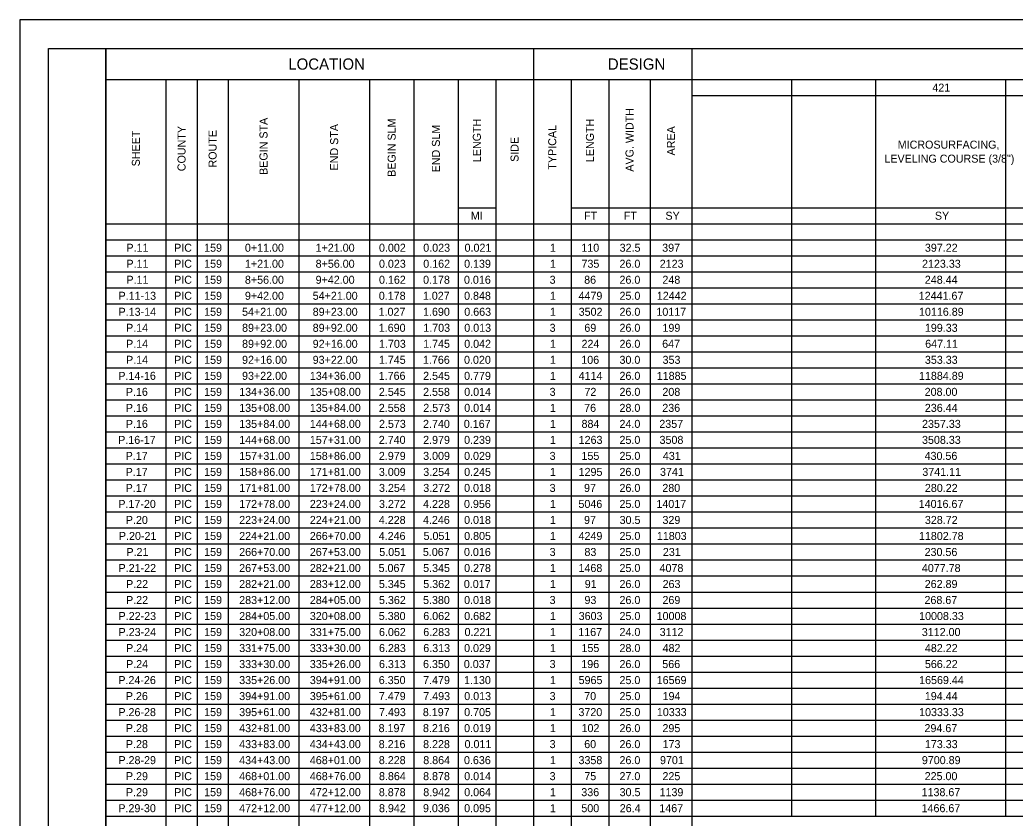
# Model space of a CAD drawing. Extents: x 0 to 34, y 0 to 22.
# Drawn here: x 0 to 17.4, y 8.04 to 22 of the extents above; entities that cross this region are included whole.
import ezdxf

# ---------------------------------------------------------------- set-up
doc = ezdxf.new("R2010")
doc.units = 0
for name, color, linetype in [('SH_Border', 7, 'Continuous'), ('SH_Cut_Line', 7, 'Continuous'), ('SH_Text', 7, 'Continuous')]:
    doc.layers.add(name, color=color, linetype=linetype)

msp = doc.modelspace()

# ---------------------------------------------------------------- linework, layer by layer
at = {"layer": 'SH_Border'}
for points in [[(0.5, 21.5), (1.5, 21.5), (1.5, 0.5), (0.5, 0.5)], [(1.5, 21.5), (33.5, 21.5), (33.5, 0.5), (1.5, 0.5)]]:
    msp.add_lwpolyline(points, close=True, dxfattribs=at)
at = {"layer": 'SH_Cut_Line'}
msp.add_lwpolyline([(0, 0), (34, 0), (34, 22), (0, 22)], close=True, dxfattribs=at)
at = {"layer": 'SH_Text'}
for p, q in [((1.5, 21.5), (32.004, 21.5)), ((1.5, 21.5), (1.5, 3.876)), ((8.978, 21.5), (8.978, 0.796)), ((11.745, 21.5), (11.745, 0.516)), ((1.5, 20.956), (32.004, 20.956)), ((2.554, 20.956), (2.554, 0.796)), ((3.098, 20.956), (3.098, 0.796)), ((3.641, 20.956), (3.641, 0.796)), ((4.876, 20.956), (4.876, 0.796)), ((6.112, 20.956), (6.112, 0.796)), ((6.886, 20.956), (6.886, 0.796)), ((7.66, 20.956), (7.66, 0.796)), ((8.319, 20.956), (8.319, 0.796)), ((9.636, 20.956), (9.636, 3.316)), ((10.295, 20.956), (10.295, 3.316)), ((11.02, 20.956), (11.02, 0.796)), ((13.491, 20.956), (13.491, 8.076)), ((14.956, 20.956), (14.956, 8.076)), ((17.229, 20.956), (17.229, 8.076)), ((11.745, 20.676), (27.474, 20.676)), ((7.66, 18.716), (8.319, 18.716)), ((9.636, 18.716), (27.474, 18.716)), ((1.5, 18.436), (32.004, 18.436)), ((1.5, 18.156), (32.004, 18.156)), ((1.5, 17.876), (32.004, 17.876)), ((1.5, 17.596), (32.004, 17.596)), ((1.5, 17.316), (32.004, 17.316)), ((1.5, 17.036), (32.004, 17.036)), ((1.5, 16.756), (32.004, 16.756)), ((1.5, 16.476), (32.004, 16.476)), ((1.5, 16.196), (32.004, 16.196)), ((1.5, 15.916), (32.004, 15.916)), ((1.5, 15.636), (32.004, 15.636)), ((1.5, 15.356), (32.004, 15.356)), ((1.5, 15.076), (32.004, 15.076)), ((1.5, 14.796), (32.004, 14.796)), ((1.5, 14.516), (32.004, 14.516)), ((1.5, 14.236), (32.004, 14.236)), ((1.5, 13.956), (32.004, 13.956)), ((1.5, 13.676), (32.004, 13.676)), ((1.5, 13.396), (32.004, 13.396)), ((1.5, 13.116), (32.004, 13.116)), ((1.5, 12.836), (32.004, 12.836)), ((1.5, 12.556), (32.004, 12.556)), ((1.5, 12.276), (32.004, 12.276)), ((1.5, 11.996), (32.004, 11.996)), ((1.5, 11.716), (32.004, 11.716)), ((1.5, 11.436), (32.004, 11.436)), ((1.5, 11.156), (32.004, 11.156)), ((1.5, 10.876), (32.004, 10.876)), ((1.5, 10.596), (32.004, 10.596)), ((1.5, 10.316), (32.004, 10.316)), ((1.5, 10.036), (32.004, 10.036)), ((1.5, 9.756), (32.004, 9.756)), ((1.5, 9.476), (32.004, 9.476)), ((1.5, 9.196), (32.004, 9.196)), ((1.5, 8.916), (32.004, 8.916)), ((1.5, 8.636), (32.004, 8.636)), ((1.5, 8.356), (32.004, 8.356)), ((1.5, 8.076), (32.004, 8.076))]:
    msp.add_line(p, q, dxfattribs=at)

# ---------------------------------------------------------------- texts
for s, height, p in [('LOCATION', 0.196, (4.692, 21.13)), ('DESIGN', 0.196, (10.279, 21.13)), ('421', 0.14, (15.952, 20.746)), ('MICROSURFACING, ', 0.14, (15.347, 19.749)), ('LEVELING COURSE (3/8")', 0.14, (15.114, 19.504)), ('MI', 0.14, (7.883, 18.506)), ('FT', 0.14, (9.865, 18.506)), ('FT', 0.14, (10.557, 18.506)), ('SY', 0.14, (11.286, 18.506)), ('SY', 0.14, (15.997, 18.506)), ('P.11', 0.14, (1.862, 17.946)), ('PIC', 0.14, (2.696, 17.946)), ('159', 0.14, (3.221, 17.946)), ('0+11.00', 0.14, (3.934, 17.946)), ('1+21.00', 0.14, (5.17, 17.946)), ('0.002', 0.14, (6.278, 17.946)), ('0.023', 0.14, (7.052, 17.946)), ('0.021', 0.14, (7.774, 17.946)), ('1', 0.14, (9.267, 17.946)), ('110', 0.14, (9.816, 17.946)), ('32.5', 0.14, (10.485, 17.946)), ('397', 0.14, (11.229, 17.946)), ('397.22', 0.14, (15.822, 17.946)), ('P.11', 0.14, (1.862, 17.666)), ('PIC', 0.14, (2.696, 17.666)), ('159', 0.14, (3.221, 17.666)), ('1+21.00', 0.14, (3.934, 17.666)), ('8+56.00', 0.14, (5.17, 17.666)), ('0.023', 0.14, (6.278, 17.666)), ('0.162', 0.14, (7.052, 17.666)), ('0.139', 0.14, (7.766, 17.666)), ('1', 0.14, (9.267, 17.666)), ('735', 0.14, (9.818, 17.666)), ('26.0', 0.14, (10.483, 17.666)), ('2123', 0.14, (11.186, 17.666)), ('2123.33', 0.14, (15.772, 17.666)), ('P.11', 0.14, (1.862, 17.386)), ('PIC', 0.14, (2.696, 17.386)), ('159', 0.14, (3.221, 17.386)), ('8+56.00', 0.14, (3.934, 17.386)), ('9+42.00', 0.14, (5.17, 17.386)), ('0.162', 0.14, (6.278, 17.386)), ('0.178', 0.14, (7.049, 17.386)), ('0.016', 0.14, (7.764, 17.386)), ('3', 0.14, (9.261, 17.386)), ('86', 0.14, (9.865, 17.386)), ('26.0', 0.14, (10.483, 17.386)), ('248', 0.14, (11.233, 17.386)), ('248.44', 0.14, (15.821, 17.386)), ('P.11-13', 0.14, (1.725, 17.106)), ('PIC', 0.14, (2.696, 17.106)), ('159', 0.14, (3.221, 17.106)), ('9+42.00', 0.14, (3.934, 17.106)), ('54+21.00', 0.14, (5.119, 17.106)), ('0.178', 0.14, (6.275, 17.106)), ('1.027', 0.14, (7.045, 17.106)), ('0.848', 0.14, (7.766, 17.106)), ('1', 0.14, (9.267, 17.106)), ('4479', 0.14, (9.767, 17.106)), ('25.0', 0.14, (10.483, 17.106)), ('12442', 0.14, (11.135, 17.106)), ('12441.67', 0.14, (15.714, 17.106)), ('P.13-14', 0.14, (1.725, 16.826)), ('PIC', 0.14, (2.696, 16.826)), ('159', 0.14, (3.221, 16.826)), ('54+21.00', 0.14, (3.884, 16.826)), ('89+23.00', 0.14, (5.119, 16.826)), ('1.027', 0.14, (6.271, 16.826)), ('1.690', 0.14, (7.048, 16.826)), ('0.663', 0.14, (7.769, 16.826)), ('1', 0.14, (9.267, 16.826)), ('3502', 0.14, (9.769, 16.826)), ('26.0', 0.14, (10.483, 16.826)), ('10117', 0.14, (11.128, 16.826)), ('10116.89', 0.14, (15.719, 16.826)), ('P.14', 0.14, (1.856, 16.546)), ('PIC', 0.14, (2.696, 16.546)), ('159', 0.14, (3.221, 16.546)), ('89+23.00', 0.14, (3.884, 16.546)), ('89+92.00', 0.14, (5.119, 16.546)), ('1.690', 0.14, (6.274, 16.546)), ('1.703', 0.14, (7.052, 16.546)), ('0.013', 0.14, (7.769, 16.546)), ('3', 0.14, (9.261, 16.546)), ('69', 0.14, (9.868, 16.546)), ('26.0', 0.14, (10.483, 16.546)), ('199', 0.14, (11.234, 16.546)), ('199.33', 0.14, (15.822, 16.546)), ('P.14', 0.14, (1.856, 16.266)), ('PIC', 0.14, (2.696, 16.266)), ('159', 0.14, (3.221, 16.266)), ('89+92.00', 0.14, (3.884, 16.266)), ('92+16.00', 0.14, (5.119, 16.266)), ('1.703', 0.14, (6.278, 16.266)), ('1.745', 0.14, (7.05, 16.266)), ('0.042', 0.14, (7.768, 16.266)), ('1', 0.14, (9.267, 16.266)), ('224', 0.14, (9.819, 16.266)), ('26.0', 0.14, (10.483, 16.266)), ('647', 0.14, (11.229, 16.266)), ('647.11', 0.14, (15.827, 16.266)), ('P.14', 0.14, (1.856, 15.986)), ('PIC', 0.14, (2.696, 15.986)), ('159', 0.14, (3.221, 15.986)), ('92+16.00', 0.14, (3.884, 15.986)), ('93+22.00', 0.14, (5.119, 15.986)), ('1.745', 0.14, (6.276, 15.986)), ('1.766', 0.14, (7.047, 15.986)), ('0.020', 0.14, (7.765, 15.986)), ('1', 0.14, (9.267, 15.986)), ('106', 0.14, (9.815, 15.986)), ('30.0', 0.14, (10.483, 15.986)), ('353', 0.14, (11.236, 15.986)), ('353.33', 0.14, (15.822, 15.986)), ('P.14-16', 0.14, (1.721, 15.706)), ('PIC', 0.14, (2.696, 15.706)), ('159', 0.14, (3.221, 15.706)), ('93+22.00', 0.14, (3.884, 15.706)), ('134+36.00', 0.14, (5.069, 15.706)), ('1.766', 0.14, (6.273, 15.706)), ('2.545', 0.14, (7.05, 15.706)), ('0.779', 0.14, (7.766, 15.706)), ('1', 0.14, (9.267, 15.706)), ('4114', 0.14, (9.769, 15.706)), ('26.0', 0.14, (10.483, 15.706)), ('11885', 0.14, (11.134, 15.706)), ('11884.89', 0.14, (15.719, 15.706)), ('P.16', 0.14, (1.852, 15.426)), ('PIC', 0.14, (2.696, 15.426)), ('159', 0.14, (3.221, 15.426)), ('134+36.00', 0.14, (3.834, 15.426)), ('135+08.00', 0.14, (5.069, 15.426)), ('2.545', 0.14, (6.276, 15.426)), ('2.558', 0.14, (7.049, 15.426)), ('0.014', 0.14, (7.768, 15.426)), ('3', 0.14, (9.261, 15.426)), ('72', 0.14, (9.87, 15.426)), ('26.0', 0.14, (10.483, 15.426)), ('208', 0.14, (11.233, 15.426)), ('208.00', 0.14, (15.818, 15.426)), ('P.16', 0.14, (1.852, 15.146)), ('PIC', 0.14, (2.696, 15.146)), ('159', 0.14, (3.221, 15.146)), ('135+08.00', 0.14, (3.834, 15.146)), ('135+84.00', 0.14, (5.069, 15.146)), ('2.558', 0.14, (6.275, 15.146)), ('2.573', 0.14, (7.052, 15.146)), ('0.014', 0.14, (7.768, 15.146)), ('1', 0.14, (9.267, 15.146)), ('76', 0.14, (9.865, 15.146)), ('28.0', 0.14, (10.483, 15.146)), ('236', 0.14, (11.231, 15.146)), ('236.44', 0.14, (15.821, 15.146)), ('P.16', 0.14, (1.852, 14.866)), ('PIC', 0.14, (2.696, 14.866)), ('159', 0.14, (3.221, 14.866)), ('135+84.00', 0.14, (3.834, 14.866)), ('144+68.00', 0.14, (5.069, 14.866)), ('2.573', 0.14, (6.278, 14.866)), ('2.740', 0.14, (7.048, 14.866)), ('0.167', 0.14, (7.761, 14.866)), ('1', 0.14, (9.267, 14.866)), ('884', 0.14, (9.819, 14.866)), ('24.0', 0.14, (10.483, 14.866)), ('2357', 0.14, (11.179, 14.866)), ('2357.33', 0.14, (15.772, 14.866)), ('P.16-17', 0.14, (1.718, 14.586)), ('PIC', 0.14, (2.696, 14.586)), ('159', 0.14, (3.221, 14.586)), ('144+68.00', 0.14, (3.834, 14.586)), ('157+31.00', 0.14, (5.069, 14.586)), ('2.740', 0.14, (6.274, 14.586)), ('2.979', 0.14, (7.05, 14.586)), ('0.239', 0.14, (7.766, 14.586)), ('1', 0.14, (9.267, 14.586)), ('1263', 0.14, (9.769, 14.586)), ('25.0', 0.14, (10.483, 14.586)), ('3508', 0.14, (11.183, 14.586)), ('3508.33', 0.14, (15.772, 14.586)), ('P.17', 0.14, (1.849, 14.306)), ('PIC', 0.14, (2.696, 14.306)), ('159', 0.14, (3.221, 14.306)), ('157+31.00', 0.14, (3.834, 14.306)), ('158+86.00', 0.14, (5.069, 14.306)), ('2.979', 0.14, (6.276, 14.306)), ('3.009', 0.14, (7.05, 14.306)), ('0.029', 0.14, (7.766, 14.306)), ('3', 0.14, (9.261, 14.306)), ('155', 0.14, (9.818, 14.306)), ('25.0', 0.14, (10.483, 14.306)), ('431', 0.14, (11.241, 14.306)), ('430.56', 0.14, (15.817, 14.306)), ('P.17', 0.14, (1.849, 14.026)), ('PIC', 0.14, (2.696, 14.026)), ('159', 0.14, (3.221, 14.026)), ('158+86.00', 0.14, (3.834, 14.026)), ('171+81.00', 0.14, (5.069, 14.026)), ('3.009', 0.14, (6.276, 14.026)), ('3.254', 0.14, (7.052, 14.026)), ('0.245', 0.14, (7.767, 14.026)), ('1', 0.14, (9.267, 14.026)), ('1295', 0.14, (9.768, 14.026)), ('26.0', 0.14, (10.483, 14.026)), ('3741', 0.14, (11.191, 14.026)), ('3741.11', 0.14, (15.777, 14.026)), ('P.17', 0.14, (1.849, 13.746)), ('PIC', 0.14, (2.696, 13.746)), ('159', 0.14, (3.221, 13.746)), ('171+81.00', 0.14, (3.834, 13.746)), ('172+78.00', 0.14, (5.069, 13.746)), ('3.254', 0.14, (6.278, 13.746)), ('3.272', 0.14, (7.052, 13.746)), ('0.018', 0.14, (7.766, 13.746)), ('3', 0.14, (9.261, 13.746)), ('97', 0.14, (9.863, 13.746)), ('26.0', 0.14, (10.483, 13.746)), ('280', 0.14, (11.232, 13.746)), ('280.22', 0.14, (15.822, 13.746)), ('P.17-20', 0.14, (1.721, 13.466)), ('PIC', 0.14, (2.696, 13.466)), ('159', 0.14, (3.221, 13.466)), ('172+78.00', 0.14, (3.834, 13.466)), ('223+24.00', 0.14, (5.069, 13.466)), ('3.272', 0.14, (6.278, 13.466)), ('4.228', 0.14, (7.049, 13.466)), ('0.956', 0.14, (7.764, 13.466)), ('1', 0.14, (9.267, 13.466)), ('5046', 0.14, (9.765, 13.466)), ('25.0', 0.14, (10.483, 13.466)), ('14017', 0.14, (11.128, 13.466)), ('14016.67', 0.14, (15.714, 13.466)), ('P.20', 0.14, (1.852, 13.186)), ('PIC', 0.14, (2.696, 13.186)), ('159', 0.14, (3.221, 13.186)), ('223+24.00', 0.14, (3.834, 13.186)), ('224+21.00', 0.14, (5.069, 13.186)), ('4.228', 0.14, (6.275, 13.186)), ('4.246', 0.14, (7.047, 13.186)), ('0.018', 0.14, (7.766, 13.186)), ('1', 0.14, (9.267, 13.186)), ('97', 0.14, (9.863, 13.186)), ('30.5', 0.14, (10.485, 13.186)), ('329', 0.14, (11.234, 13.186)), ('328.72', 0.14, (15.822, 13.186)), ('P.20-21', 0.14, (1.731, 12.906)), ('PIC', 0.14, (2.696, 12.906)), ('159', 0.14, (3.221, 12.906)), ('224+21.00', 0.14, (3.834, 12.906)), ('266+70.00', 0.14, (5.069, 12.906)), ('4.246', 0.14, (6.273, 12.906)), ('5.051', 0.14, (7.057, 12.906)), ('0.805', 0.14, (7.767, 12.906)), ('1', 0.14, (9.267, 12.906)), ('4249', 0.14, (9.767, 12.906)), ('25.0', 0.14, (10.483, 12.906)), ('11803', 0.14, (11.136, 12.906)), ('11802.78', 0.14, (15.718, 12.906)), ('P.21', 0.14, (1.862, 12.626)), ('PIC', 0.14, (2.696, 12.626)), ('159', 0.14, (3.221, 12.626)), ('266+70.00', 0.14, (3.834, 12.626)), ('267+53.00', 0.14, (5.069, 12.626)), ('5.051', 0.14, (6.283, 12.626)), ('5.067', 0.14, (7.045, 12.626)), ('0.016', 0.14, (7.764, 12.626)), ('3', 0.14, (9.261, 12.626)), ('83', 0.14, (9.87, 12.626)), ('25.0', 0.14, (10.483, 12.626)), ('231', 0.14, (11.241, 12.626)), ('230.56', 0.14, (15.817, 12.626)), ('P.21-22', 0.14, (1.725, 12.346)), ('PIC', 0.14, (2.696, 12.346)), ('159', 0.14, (3.221, 12.346)), ('267+53.00', 0.14, (3.834, 12.346)), ('282+21.00', 0.14, (5.069, 12.346)), ('5.067', 0.14, (6.271, 12.346)), ('5.345', 0.14, (7.05, 12.346)), ('0.278', 0.14, (7.766, 12.346)), ('1', 0.14, (9.267, 12.346)), ('1468', 0.14, (9.766, 12.346)), ('25.0', 0.14, (10.483, 12.346)), ('4078', 0.14, (11.183, 12.346)), ('4077.78', 0.14, (15.769, 12.346)), ('P.22', 0.14, (1.856, 12.066)), ('PIC', 0.14, (2.696, 12.066)), ('159', 0.14, (3.221, 12.066)), ('282+21.00', 0.14, (3.834, 12.066)), ('283+12.00', 0.14, (5.069, 12.066)), ('5.345', 0.14, (6.276, 12.066)), ('5.362', 0.14, (7.052, 12.066)), ('0.017', 0.14, (7.761, 12.066)), ('1', 0.14, (9.267, 12.066)), ('91', 0.14, (9.875, 12.066)), ('26.0', 0.14, (10.483, 12.066)), ('263', 0.14, (11.236, 12.066)), ('262.89', 0.14, (15.819, 12.066)), ('P.22', 0.14, (1.856, 11.786)), ('PIC', 0.14, (2.696, 11.786)), ('159', 0.14, (3.221, 11.786)), ('283+12.00', 0.14, (3.834, 11.786)), ('284+05.00', 0.14, (5.069, 11.786)), ('5.362', 0.14, (6.278, 11.786)), ('5.380', 0.14, (7.048, 11.786)), ('0.018', 0.14, (7.766, 11.786)), ('3', 0.14, (9.261, 11.786)), ('93', 0.14, (9.87, 11.786)), ('26.0', 0.14, (10.483, 11.786)), ('269', 0.14, (11.234, 11.786)), ('268.67', 0.14, (15.815, 11.786)), ('P.22-23', 0.14, (1.725, 11.506)), ('PIC', 0.14, (2.696, 11.506)), ('159', 0.14, (3.221, 11.506)), ('284+05.00', 0.14, (3.834, 11.506)), ('320+08.00', 0.14, (5.069, 11.506)), ('5.380', 0.14, (6.274, 11.506)), ('6.062', 0.14, (7.052, 11.506)), ('0.682', 0.14, (7.768, 11.506)), ('1', 0.14, (9.267, 11.506)), ('3603', 0.14, (9.769, 11.506)), ('25.0', 0.14, (10.483, 11.506)), ('10008', 0.14, (11.132, 11.506)), ('10008.33', 0.14, (15.721, 11.506)), ('P.23-24', 0.14, (1.725, 11.226)), ('PIC', 0.14, (2.696, 11.226)), ('159', 0.14, (3.221, 11.226)), ('320+08.00', 0.14, (3.834, 11.226)), ('331+75.00', 0.14, (5.069, 11.226)), ('6.062', 0.14, (6.278, 11.226)), ('6.283', 0.14, (7.052, 11.226)), ('0.221', 0.14, (7.774, 11.226)), ('1', 0.14, (9.267, 11.226)), ('1167', 0.14, (9.762, 11.226)), ('24.0', 0.14, (10.483, 11.226)), ('3112', 0.14, (11.185, 11.226)), ('3112.00', 0.14, (15.768, 11.226)), ('P.24', 0.14, (1.856, 10.946)), ('PIC', 0.14, (2.696, 10.946)), ('159', 0.14, (3.221, 10.946)), ('331+75.00', 0.14, (3.834, 10.946)), ('333+30.00', 0.14, (5.069, 10.946)), ('6.283', 0.14, (6.278, 10.946)), ('6.313', 0.14, (7.052, 10.946)), ('0.029', 0.14, (7.766, 10.946)), ('1', 0.14, (9.267, 10.946)), ('155', 0.14, (9.818, 10.946)), ('28.0', 0.14, (10.483, 10.946)), ('482', 0.14, (11.236, 10.946)), ('482.22', 0.14, (15.822, 10.946)), ('P.24', 0.14, (1.856, 10.666)), ('PIC', 0.14, (2.696, 10.666)), ('159', 0.14, (3.221, 10.666)), ('333+30.00', 0.14, (3.834, 10.666)), ('335+26.00', 0.14, (5.069, 10.666)), ('6.313', 0.14, (6.278, 10.666)), ('6.350', 0.14, (7.048, 10.666)), ('0.037', 0.14, (7.761, 10.666)), ('3', 0.14, (9.261, 10.666)), ('196', 0.14, (9.815, 10.666)), ('26.0', 0.14, (10.483, 10.666)), ('566', 0.14, (11.231, 10.666)), ('566.22', 0.14, (15.822, 10.666)), ('P.24-26', 0.14, (1.721, 10.386)), ('PIC', 0.14, (2.696, 10.386)), ('159', 0.14, (3.221, 10.386)), ('335+26.00', 0.14, (3.834, 10.386)), ('394+91.00', 0.14, (5.069, 10.386)), ('6.350', 0.14, (6.274, 10.386)), ('7.479', 0.14, (7.05, 10.386)), ('1.130', 0.14, (7.765, 10.386)), ('1', 0.14, (9.267, 10.386)), ('5965', 0.14, (9.768, 10.386)), ('25.0', 0.14, (10.483, 10.386)), ('16569', 0.14, (11.133, 10.386)), ('16569.44', 0.14, (15.721, 10.386)), ('P.26', 0.14, (1.852, 10.106)), ('PIC', 0.14, (2.696, 10.106)), ('159', 0.14, (3.221, 10.106)), ('394+91.00', 0.14, (3.834, 10.106)), ('395+61.00', 0.14, (5.069, 10.106)), ('7.479', 0.14, (6.276, 10.106)), ('7.493', 0.14, (7.052, 10.106)), ('0.013', 0.14, (7.769, 10.106)), ('3', 0.14, (9.261, 10.106)), ('70', 0.14, (9.866, 10.106)), ('25.0', 0.14, (10.483, 10.106)), ('194', 0.14, (11.236, 10.106)), ('194.44', 0.14, (15.821, 10.106)), ('P.26-28', 0.14, (1.722, 9.826)), ('PIC', 0.14, (2.696, 9.826)), ('159', 0.14, (3.221, 9.826)), ('395+61.00', 0.14, (3.834, 9.826)), ('432+81.00', 0.14, (5.069, 9.826)), ('7.493', 0.14, (6.278, 9.826)), ('8.197', 0.14, (7.045, 9.826)), ('0.705', 0.14, (7.767, 9.826)), ('1', 0.14, (9.267, 9.826)), ('3720', 0.14, (9.765, 9.826)), ('25.0', 0.14, (10.483, 9.826)), ('10333', 0.14, (11.136, 9.826)), ('10333.33', 0.14, (15.721, 9.826)), ('P.28', 0.14, (1.853, 9.546)), ('PIC', 0.14, (2.696, 9.546)), ('159', 0.14, (3.221, 9.546)), ('432+81.00', 0.14, (3.834, 9.546)), ('433+83.00', 0.14, (5.069, 9.546)), ('8.197', 0.14, (6.271, 9.546)), ('8.216', 0.14, (7.047, 9.546)), ('0.019', 0.14, (7.766, 9.546)), ('1', 0.14, (9.267, 9.546)), ('102', 0.14, (9.819, 9.546)), ('26.0', 0.14, (10.483, 9.546)), ('295', 0.14, (11.234, 9.546)), ('294.67', 0.14, (15.815, 9.546)), ('P.28', 0.14, (1.853, 9.266)), ('PIC', 0.14, (2.696, 9.266)), ('159', 0.14, (3.221, 9.266)), ('433+83.00', 0.14, (3.834, 9.266)), ('434+43.00', 0.14, (5.069, 9.266)), ('8.216', 0.14, (6.273, 9.266)), ('8.228', 0.14, (7.049, 9.266)), ('0.011', 0.14, (7.774, 9.266)), ('3', 0.14, (9.261, 9.266)), ('60', 0.14, (9.866, 9.266)), ('26.0', 0.14, (10.483, 9.266)), ('173', 0.14, (11.236, 9.266)), ('173.33', 0.14, (15.822, 9.266)), ('P.28-29', 0.14, (1.723, 8.986)), ('PIC', 0.14, (2.696, 8.986)), ('159', 0.14, (3.221, 8.986)), ('434+43.00', 0.14, (3.834, 8.986)), ('468+01.00', 0.14, (5.069, 8.986)), ('8.228', 0.14, (6.275, 8.986)), ('8.864', 0.14, (7.052, 8.986)), ('0.636', 0.14, (7.764, 8.986)), ('1', 0.14, (9.267, 8.986)), ('3358', 0.14, (9.766, 8.986)), ('26.0', 0.14, (10.483, 8.986)), ('9701', 0.14, (11.191, 8.986)), ('9700.89', 0.14, (15.769, 8.986)), ('P.29', 0.14, (1.854, 8.706)), ('PIC', 0.14, (2.696, 8.706)), ('159', 0.14, (3.221, 8.706)), ('468+01.00', 0.14, (3.834, 8.706)), ('468+76.00', 0.14, (5.069, 8.706)), ('8.864', 0.14, (6.278, 8.706)), ('8.878', 0.14, (7.049, 8.706)), ('0.014', 0.14, (7.768, 8.706)), ('3', 0.14, (9.261, 8.706)), ('75', 0.14, (9.868, 8.706)), ('27.0', 0.14, (10.483, 8.706)), ('225', 0.14, (11.234, 8.706)), ('225.00', 0.14, (15.818, 8.706)), ('P.29', 0.14, (1.854, 8.426)), ('PIC', 0.14, (2.696, 8.426)), ('159', 0.14, (3.221, 8.426)), ('468+76.00', 0.14, (3.834, 8.426)), ('472+12.00', 0.14, (5.069, 8.426)), ('8.878', 0.14, (6.275, 8.426)), ('8.942', 0.14, (7.052, 8.426)), ('0.064', 0.14, (7.768, 8.426)), ('1', 0.14, (9.267, 8.426)), ('336', 0.14, (9.815, 8.426)), ('30.5', 0.14, (10.485, 8.426)), ('1139', 0.14, (11.183, 8.426)), ('1138.67', 0.14, (15.764, 8.426)), ('P.29-30', 0.14, (1.721, 8.146)), ('PIC', 0.14, (2.696, 8.146)), ('159', 0.14, (3.221, 8.146)), ('472+12.00', 0.14, (3.834, 8.146)), ('477+12.00', 0.14, (5.069, 8.146)), ('8.942', 0.14, (6.278, 8.146)), ('9.036', 0.14, (7.047, 8.146)), ('0.095', 0.14, (7.767, 8.146)), ('1', 0.14, (9.267, 8.146)), ('500', 0.14, (9.816, 8.146)), ('26.4', 0.14, (10.487, 8.146)), ('1467', 0.14, (11.179, 8.146)), ('1466.67', 0.14, (15.764, 8.146))]:
    msp.add_text(s, height=height, dxfattribs=at).set_placement(p)
for s, p in [('AVG. WIDTH', (10.728, 19.346)), ('BEGIN STA', (4.329, 19.29)), ('BEGIN SLM', (6.569, 19.256)), ('LENGTH', (8.059, 19.513)), ('LENGTH', (10.036, 19.513)), ('SHEET', (2.097, 19.439)), ('COUNTY', (2.896, 19.354)), ('ROUTE', (3.439, 19.419)), ('END STA', (5.564, 19.368)), ('END SLM', (7.343, 19.334)), ('TYPICAL', (9.377, 19.382)), ('AREA', (11.452, 19.63)), ('SIDE', (8.718, 19.518))]:
    msp.add_text(s, height=0.14, rotation=90, dxfattribs=at).set_placement(p)

doc.saveas('drawing.dxf')
